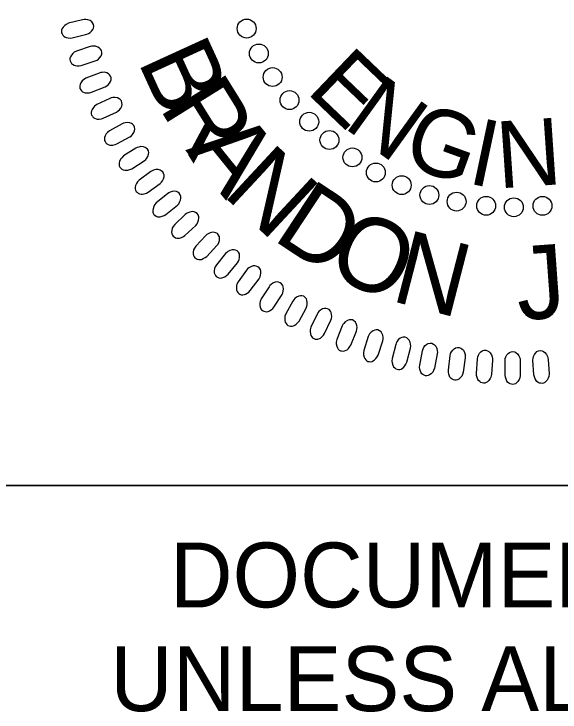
# Model space of a CAD drawing. Extents: x 505602 to 507286, y 483109 to 484209.
# Drawn here: x 507076.9 to 507123.2, y 484026.9 to 484086.2 of the extents above; entities that cross this region are included whole.
import ezdxf

# ---------------------------------------------------------------- set-up
doc = ezdxf.new("R2010")
doc.units = 0
for name, color, linetype in [('Sheet PE Seal Cell', 7, 'Continuous'), ('Sheet Profile CELL', 7, 'Continuous'), ('Sheet Sticker Exception Certification CELL', 7, 'Continuous')]:
    doc.layers.add(name, color=color, linetype=linetype)

msp = doc.modelspace()

# ---------------------------------------------------------------- linework, layer by layer
at = {"layer": 'Sheet PE Seal Cell'}
for points in [[(507082.689, 484085.667), (507081.501, 484085.363), (507081.298, 484085.272), (507081.175, 484085.187), (507081.039, 484085.036), (507080.957, 484084.915), (507080.907, 484084.786), (507080.895, 484084.675), (507080.903, 484084.561), (507080.95, 484084.458), (507081.009, 484084.35), (507081.093, 484084.263), (507081.216, 484084.186), (507081.308, 484084.148), (507081.469, 484084.12), (507081.658, 484084.107), (507081.818, 484084.125), (507083.037, 484084.429), (507083.196, 484084.493), (507083.32, 484084.572), (507083.452, 484084.698), (507083.56, 484084.841), (507083.613, 484084.955), (507083.632, 484085.122), (507083.614, 484085.272), (507083.538, 484085.407), (507083.464, 484085.496), (507083.336, 484085.595), (507083.142, 484085.668), (507082.951, 484085.689), (507082.818, 484085.685)], [(507083.343, 484083.384), (507082.176, 484083.005), (507081.979, 484082.902), (507081.862, 484082.81), (507081.735, 484082.65), (507081.661, 484082.523), (507081.62, 484082.392), (507081.615, 484082.281), (507081.63, 484082.168), (507081.684, 484082.068), (507081.749, 484081.963), (507081.838, 484081.882), (507081.966, 484081.813), (507082.059, 484081.78), (507082.223, 484081.763), (507082.412, 484081.762), (507082.571, 484081.789), (507083.768, 484082.17), (507083.922, 484082.244), (507084.042, 484082.33), (507084.165, 484082.464), (507084.263, 484082.614), (507084.31, 484082.731), (507084.318, 484082.899), (507084.291, 484083.047), (507084.207, 484083.177), (507084.127, 484083.261), (507083.993, 484083.351), (507083.795, 484083.412), (507083.603, 484083.421), (507083.471, 484083.409)], [(507084.102, 484081.146), (507082.961, 484080.696), (507082.77, 484080.58), (507082.659, 484080.48), (507082.543, 484080.313), (507082.477, 484080.182), (507082.444, 484080.049), (507082.446, 484079.937), (507082.468, 484079.825), (507082.528, 484079.729), (507082.6, 484079.628), (507082.693, 484079.553), (507082.825, 484079.493), (507082.921, 484079.466), (507083.086, 484079.459), (507083.274, 484079.469), (507083.431, 484079.507), (507084.602, 484079.962), (507084.752, 484080.045), (507084.865, 484080.138), (507084.98, 484080.28), (507085.069, 484080.436), (507085.108, 484080.556), (507085.105, 484080.724), (507085.069, 484080.87), (507084.977, 484080.994), (507084.892, 484081.073), (507084.753, 484081.155), (507084.551, 484081.203), (507084.359, 484081.2), (507084.228, 484081.18)], [(507085.001, 484078.987), (507083.891, 484078.465), (507083.709, 484078.338), (507083.604, 484078.231), (507083.499, 484078.057), (507083.441, 484077.923), (507083.416, 484077.787), (507083.425, 484077.676), (507083.454, 484077.566), (507083.52, 484077.473), (507083.598, 484077.377), (507083.697, 484077.308), (507083.832, 484077.256), (507083.929, 484077.235), (507084.093, 484077.238), (507084.281, 484077.261), (507084.435, 484077.308), (507085.576, 484077.836), (507085.719, 484077.929), (507085.827, 484078.029), (507085.932, 484078.177), (507086.012, 484078.338), (507086.043, 484078.461), (507086.03, 484078.628), (507085.984, 484078.772), (507085.884, 484078.89), (507085.794, 484078.964), (507085.651, 484079.037), (507085.446, 484079.072), (507085.255, 484079.057), (507085.125, 484079.029)], [(507086.049, 484076.838), (507084.973, 484076.248), (507084.799, 484076.11), (507084.702, 484075.996), (507084.607, 484075.817), (507084.558, 484075.678), (507084.542, 484075.542), (507084.557, 484075.431), (507084.594, 484075.323), (507084.666, 484075.235), (507084.75, 484075.144), (507084.852, 484075.081), (507084.99, 484075.037), (507085.089, 484075.023), (507085.252, 484075.036), (507085.438, 484075.071), (507085.589, 484075.127), (507086.694, 484075.726), (507086.832, 484075.828), (507086.932, 484075.934), (507087.029, 484076.089), (507087.097, 484076.254), (507087.121, 484076.378), (507087.097, 484076.545), (507087.043, 484076.686), (507086.936, 484076.797), (507086.842, 484076.865), (507086.693, 484076.928), (507086.487, 484076.951), (507086.297, 484076.924), (507086.169, 484076.888)], [(507087.205, 484074.764), (507086.169, 484074.106), (507086.003, 484073.958), (507085.914, 484073.839), (507085.83, 484073.653), (507085.79, 484073.513), (507085.783, 484073.375), (507085.805, 484073.265), (507085.848, 484073.16), (507085.926, 484073.076), (507086.015, 484072.991), (507086.121, 484072.935), (507086.261, 484072.9), (507086.36, 484072.892), (507086.523, 484072.915), (507086.707, 484072.961), (507086.853, 484073.027), (507087.919, 484073.694), (507088.05, 484073.803), (507088.144, 484073.917), (507088.23, 484074.077), (507088.288, 484074.247), (507088.304, 484074.372), (507088.27, 484074.537), (507088.207, 484074.673), (507088.093, 484074.778), (507087.995, 484074.84), (507087.842, 484074.894), (507087.635, 484074.904), (507087.447, 484074.865), (507087.322, 484074.82)], [(507088.482, 484072.789), (507087.488, 484072.068), (507087.333, 484071.909), (507087.25, 484071.785), (507087.179, 484071.594), (507087.148, 484071.451), (507087.149, 484071.313), (507087.178, 484071.206), (507087.228, 484071.102), (507087.31, 484071.024), (507087.405, 484070.945), (507087.515, 484070.895), (507087.657, 484070.869), (507087.756, 484070.868), (507087.917, 484070.901), (507088.097, 484070.958), (507088.24, 484071.033), (507089.261, 484071.766), (507089.385, 484071.884), (507089.471, 484072.002), (507089.548, 484072.168), (507089.595, 484072.341), (507089.603, 484072.466), (507089.559, 484072.629), (507089.487, 484072.762), (507089.367, 484072.859), (507089.265, 484072.914), (507089.11, 484072.959), (507088.903, 484072.956), (507088.717, 484072.905), (507088.595, 484072.853)], [(507089.885, 484070.907), (507088.939, 484070.125), (507088.794, 484069.957), (507088.72, 484069.828), (507088.661, 484069.633), (507088.638, 484069.489), (507088.648, 484069.352), (507088.684, 484069.246), (507088.74, 484069.146), (507088.827, 484069.073), (507088.926, 484069), (507089.039, 484068.957), (507089.182, 484068.94), (507089.282, 484068.945), (507089.44, 484068.988), (507089.616, 484069.057), (507089.754, 484069.14), (507090.727, 484069.936), (507090.844, 484070.061), (507090.922, 484070.185), (507090.988, 484070.355), (507091.025, 484070.531), (507091.024, 484070.656), (507090.97, 484070.816), (507090.89, 484070.943), (507090.764, 484071.033), (507090.659, 484071.082), (507090.501, 484071.117), (507090.295, 484071.101), (507090.113, 484071.038), (507089.994, 484070.978)], [(507091.395, 484069.137), (507090.5, 484068.297), (507090.366, 484068.12), (507090.3, 484067.987), (507090.253, 484067.789), (507090.24, 484067.643), (507090.258, 484067.506), (507090.301, 484067.402), (507090.363, 484067.307), (507090.454, 484067.239), (507090.558, 484067.172), (507090.673, 484067.137), (507090.818, 484067.129), (507090.916, 484067.14), (507091.072, 484067.193), (507091.244, 484067.272), (507091.375, 484067.365), (507092.296, 484068.22), (507092.405, 484068.352), (507092.476, 484068.481), (507092.531, 484068.655), (507092.556, 484068.832), (507092.548, 484068.957), (507092.484, 484069.113), (507092.396, 484069.236), (507092.265, 484069.317), (507092.157, 484069.359), (507091.997, 484069.384), (507091.792, 484069.355), (507091.614, 484069.281), (507091.5, 484069.214)], [(507093.131, 484067.359), (507092.29, 484066.464), (507092.167, 484066.279), (507092.11, 484066.142), (507092.075, 484065.941), (507092.071, 484065.794), (507092.098, 484065.66), (507092.147, 484065.559), (507092.215, 484065.468), (507092.31, 484065.406), (507092.419, 484065.346), (507092.535, 484065.317), (507092.68, 484065.319), (507092.778, 484065.335), (507092.93, 484065.398), (507093.096, 484065.488), (507093.222, 484065.589), (507094.088, 484066.5), (507094.187, 484066.639), (507094.25, 484066.772), (507094.294, 484066.949), (507094.308, 484067.127), (507094.292, 484067.252), (507094.219, 484067.403), (507094.123, 484067.521), (507093.987, 484067.593), (507093.876, 484067.628), (507093.716, 484067.644), (507093.513, 484067.601), (507093.34, 484067.517), (507093.23, 484067.443)], [(507094.821, 484065.829), (507094.038, 484064.883), (507093.927, 484064.69), (507093.878, 484064.55), (507093.856, 484064.348), (507093.862, 484064.201), (507093.897, 484064.068), (507093.952, 484063.97), (507094.026, 484063.883), (507094.124, 484063.828), (507094.236, 484063.775), (507094.354, 484063.754), (507094.499, 484063.764), (507094.596, 484063.787), (507094.743, 484063.859), (507094.903, 484063.959), (507095.023, 484064.068), (507095.83, 484065.032), (507095.921, 484065.176), (507095.974, 484065.313), (507096.008, 484065.492), (507096.011, 484065.671), (507095.986, 484065.796), (507095.903, 484065.941), (507095.801, 484066.052), (507095.661, 484066.116), (507095.547, 484066.145), (507095.386, 484066.149), (507095.187, 484066.095), (507095.019, 484065.999), (507094.914, 484065.919)], [(507096.601, 484064.428), (507095.88, 484063.435), (507095.781, 484063.236), (507095.741, 484063.092), (507095.732, 484062.889), (507095.747, 484062.743), (507095.79, 484062.613), (507095.851, 484062.519), (507095.93, 484062.437), (507096.033, 484062.387), (507096.148, 484062.341), (507096.267, 484062.327), (507096.41, 484062.347), (507096.506, 484062.376), (507096.648, 484062.458), (507096.802, 484062.568), (507096.914, 484062.683), (507097.659, 484063.695), (507097.74, 484063.846), (507097.786, 484063.986), (507097.808, 484064.167), (507097.8, 484064.346), (507097.767, 484064.467), (507097.676, 484064.609), (507097.566, 484064.713), (507097.422, 484064.768), (507097.308, 484064.789), (507097.147, 484064.784), (507096.95, 484064.716), (507096.79, 484064.611), (507096.69, 484064.523)], [(507098.503, 484063.015), (507097.846, 484061.979), (507097.759, 484061.774), (507097.728, 484061.628), (507097.732, 484061.424), (507097.756, 484061.28), (507097.808, 484061.153), (507097.874, 484061.062), (507097.959, 484060.986), (507098.063, 484060.942), (507098.181, 484060.903), (507098.301, 484060.898), (507098.443, 484060.926), (507098.536, 484060.962), (507098.673, 484061.051), (507098.82, 484061.171), (507098.924, 484061.294), (507099.604, 484062.35), (507099.676, 484062.506), (507099.713, 484062.648), (507099.723, 484062.83), (507099.703, 484063.008), (507099.663, 484063.128), (507099.564, 484063.263), (507099.448, 484063.359), (507099.3, 484063.406), (507099.185, 484063.42), (507099.025, 484063.404), (507098.833, 484063.325), (507098.679, 484063.209), (507098.585, 484063.116)], [(507100.521, 484061.799), (507099.93, 484060.724), (507099.857, 484060.514), (507099.835, 484060.367), (507099.852, 484060.164), (507099.884, 484060.021), (507099.944, 484059.897), (507100.016, 484059.811), (507100.105, 484059.74), (507100.212, 484059.704), (507100.332, 484059.672), (507100.452, 484059.673), (507100.592, 484059.711), (507100.683, 484059.752), (507100.814, 484059.851), (507100.953, 484059.979), (507101.05, 484060.108), (507101.662, 484061.206), (507101.723, 484061.365), (507101.751, 484061.509), (507101.75, 484061.692), (507101.72, 484061.868), (507101.673, 484061.985), (507101.564, 484062.113), (507101.442, 484062.202), (507101.292, 484062.24), (507101.176, 484062.247), (507101.017, 484062.221), (507100.831, 484062.129), (507100.685, 484062.005), (507100.596, 484061.906)], [(507102.58, 484060.693), (507102.058, 484059.583), (507101.998, 484059.369), (507101.986, 484059.22), (507102.015, 484059.018), (507102.056, 484058.878), (507102.124, 484058.758), (507102.201, 484058.677), (507102.295, 484058.612), (507102.404, 484058.582), (507102.525, 484058.558), (507102.645, 484058.567), (507102.783, 484058.613), (507102.871, 484058.66), (507102.995, 484058.766), (507103.126, 484058.903), (507103.215, 484059.038), (507103.757, 484060.172), (507103.808, 484060.335), (507103.827, 484060.48), (507103.814, 484060.663), (507103.773, 484060.837), (507103.718, 484060.951), (507103.602, 484061.071), (507103.474, 484061.154), (507103.323, 484061.181), (507103.206, 484061.18), (507103.049, 484061.145), (507102.869, 484061.042), (507102.732, 484060.908), (507102.65, 484060.804)], [(507104.708, 484059.685), (507104.256, 484058.544), (507104.21, 484058.326), (507104.207, 484058.177), (507104.249, 484057.978), (507104.298, 484057.84), (507104.374, 484057.725), (507104.456, 484057.649), (507104.553, 484057.589), (507104.664, 484057.567), (507104.787, 484057.55), (507104.906, 484057.567), (507105.04, 484057.622), (507105.125, 484057.674), (507105.243, 484057.788), (507105.364, 484057.933), (507105.444, 484058.073), (507105.914, 484059.238), (507105.956, 484059.404), (507105.965, 484059.55), (507105.941, 484059.732), (507105.888, 484059.903), (507105.827, 484060.013), (507105.703, 484060.127), (507105.571, 484060.2), (507105.418, 484060.218), (507105.302, 484060.21), (507105.147, 484060.164), (507104.974, 484060.051), (507104.845, 484059.908), (507104.77, 484059.799)], [(507106.917, 484058.782), (507106.537, 484057.616), (507106.505, 484057.395), (507106.511, 484057.246), (507106.565, 484057.05), (507106.624, 484056.916), (507106.706, 484056.805), (507106.793, 484056.736), (507106.894, 484056.682), (507107.006, 484056.666), (507107.13, 484056.657), (507107.247, 484056.681), (507107.378, 484056.745), (507107.459, 484056.802), (507107.57, 484056.923), (507107.682, 484057.076), (507107.753, 484057.22), (507108.149, 484058.413), (507108.18, 484058.581), (507108.18, 484058.728), (507108.144, 484058.907), (507108.081, 484059.074), (507108.013, 484059.181), (507107.882, 484059.286), (507107.746, 484059.351), (507107.592, 484059.36), (507107.477, 484059.344), (507107.325, 484059.289), (507107.159, 484059.165), (507107.039, 484059.014), (507106.971, 484058.901)], [(507109.25, 484058.109), (507108.944, 484056.921), (507108.926, 484056.7), (507108.941, 484056.551), (507109.008, 484056.359), (507109.074, 484056.228), (507109.164, 484056.124), (507109.255, 484056.058), (507109.358, 484056.011), (507109.472, 484056.003), (507109.595, 484056.003), (507109.711, 484056.034), (507109.837, 484056.105), (507109.915, 484056.166), (507110.018, 484056.295), (507110.12, 484056.454), (507110.182, 484056.603), (507110.502, 484057.818), (507110.522, 484057.988), (507110.513, 484058.134), (507110.466, 484058.311), (507110.393, 484058.474), (507110.318, 484058.576), (507110.181, 484058.673), (507110.042, 484058.729), (507109.886, 484058.728), (507109.773, 484058.705), (507109.625, 484058.641), (507109.467, 484058.506), (507109.357, 484058.349), (507109.296, 484058.231)], [(507112.772, 484057.322), (507112.541, 484056.116), (507112.463, 484055.908), (507112.386, 484055.781), (507112.244, 484055.635), (507112.128, 484055.546), (507112.003, 484055.489), (507111.892, 484055.469), (507111.778, 484055.471), (507111.673, 484055.511), (507111.56, 484055.563), (507111.469, 484055.641), (507111.385, 484055.759), (507111.341, 484055.848), (507111.303, 484056.008), (507111.278, 484056.196), (507111.286, 484056.357), (507111.514, 484057.592), (507111.568, 484057.755), (507111.639, 484057.883), (507111.757, 484058.023), (507111.893, 484058.139), (507112.003, 484058.2), (507112.168, 484058.229), (507112.32, 484058.22), (507112.458, 484058.153), (507112.552, 484058.084), (507112.658, 484057.963), (507112.743, 484057.774), (507112.776, 484057.584), (507112.781, 484057.452)], [(507115.138, 484056.996), (507114.983, 484055.778), (507114.919, 484055.566), (507114.849, 484055.433), (507114.717, 484055.279), (507114.607, 484055.183), (507114.485, 484055.117), (507114.377, 484055.091), (507114.263, 484055.086), (507114.155, 484055.12), (507114.039, 484055.164), (507113.943, 484055.236), (507113.852, 484055.349), (507113.802, 484055.436), (507113.754, 484055.593), (507113.718, 484055.778), (507113.715, 484055.939), (507113.866, 484057.186), (507113.909, 484057.352), (507113.972, 484057.485), (507114.08, 484057.632), (507114.209, 484057.757), (507114.316, 484057.823), (507114.479, 484057.863), (507114.63, 484057.864), (507114.773, 484057.805), (507114.871, 484057.743), (507114.985, 484057.628), (507115.081, 484057.445), (507115.126, 484057.258), (507115.139, 484057.126)], [(507117.455, 484056.798), (507117.377, 484055.574), (507117.326, 484055.358), (507117.265, 484055.221), (507117.143, 484055.059), (507117.039, 484054.955), (507116.922, 484054.883), (507116.815, 484054.849), (507116.701, 484054.837), (507116.591, 484054.864), (507116.474, 484054.901), (507116.373, 484054.967), (507116.275, 484055.074), (507116.22, 484055.157), (507116.162, 484055.311), (507116.114, 484055.494), (507116.102, 484055.655), (507116.173, 484056.909), (507116.207, 484057.077), (507116.261, 484057.213), (507116.36, 484057.367), (507116.48, 484057.499), (507116.583, 484057.573), (507116.743, 484057.622), (507116.894, 484057.633), (507117.041, 484057.583), (507117.141, 484057.527), (507117.262, 484057.42), (507117.37, 484057.243), (507117.427, 484057.059), (507117.448, 484056.929)], [(507119.808, 484056.726), (507119.808, 484055.499), (507119.77, 484055.281), (507119.718, 484055.14), (507119.606, 484054.971), (507119.508, 484054.861), (507119.396, 484054.781), (507119.292, 484054.742), (507119.18, 484054.722), (507119.068, 484054.742), (507118.948, 484054.772), (507118.843, 484054.831), (507118.738, 484054.932), (507118.679, 484055.011), (507118.611, 484055.161), (507118.552, 484055.34), (507118.529, 484055.5), (507118.522, 484056.756), (507118.545, 484056.926), (507118.59, 484057.065), (507118.679, 484057.225), (507118.791, 484057.365), (507118.889, 484057.445), (507119.046, 484057.504), (507119.196, 484057.524), (507119.345, 484057.484), (507119.45, 484057.434), (507119.577, 484057.335), (507119.696, 484057.165), (507119.764, 484056.985), (507119.793, 484056.856)], [(507122.175, 484056.849), (507122.251, 484055.624), (507122.228, 484055.403), (507122.185, 484055.26), (507122.083, 484055.084), (507121.994, 484054.968), (507121.886, 484054.882), (507121.785, 484054.836), (507121.674, 484054.809), (507121.561, 484054.822), (507121.44, 484054.844), (507121.331, 484054.897), (507121.22, 484054.991), (507121.156, 484055.066), (507121.08, 484055.211), (507121.009, 484055.387), (507120.976, 484055.545), (507120.89, 484056.798), (507120.902, 484056.969), (507120.938, 484057.111), (507121.018, 484057.276), (507121.121, 484057.422), (507121.213, 484057.508), (507121.366, 484057.578), (507121.514, 484057.607), (507121.665, 484057.576), (507121.773, 484057.533), (507121.906, 484057.442), (507122.036, 484057.279), (507122.115, 484057.104), (507122.153, 484056.977)]]:
    msp.add_lwpolyline(points, close=True, dxfattribs=at)
for centre in [(507096.606, 484084.915), (507097.641, 484082.804), (507098.81, 484080.8), (507100.242, 484078.847), (507101.914, 484077.014), (507103.625, 484075.46), (507105.576, 484073.986), (507107.566, 484072.71), (507109.755, 484071.634), (507112.104, 484070.796), (507114.413, 484070.238), (507116.921, 484069.879), (507119.27, 484069.758), (507121.699, 484069.877)]:
    msp.add_circle(centre, 0.801, dxfattribs=at)
at = {"layer": 'Sheet Profile CELL'}
msp.add_lwpolyline([(507069.03, 484158.662), (507169.08, 484158.662), (507169.08, 484046.162), (507069.03, 484046.162)], close=True, dxfattribs=at)
at = {"layer": 'Sheet Sticker Exception Certification CELL'}
msp.add_line((507069.03, 484046.162), (507269.067, 484046.162), dxfattribs=at)
msp.add_line((507069.03, 484046.162), (507269.067, 484046.162), dxfattribs=at)

# ---------------------------------------------------------------- texts
at = {"layer": 'Sheet PE Seal Cell'}
for s, height, rotation, p in [('B', 6.236, 294.5897, (507087.323, 484082.187)), ('E', 5.669, 316.26559, (507101.563, 484079.565)), ('R', 6.236, 301.86473, (507089.134, 484078.23)), ('N', 5.669, 324.20538, (507104.698, 484076.61)), ('G', 5.669, 340.08498, (507109.592, 484073.512)), ('I', 5.669, 348.02477, (507115.221, 484071.822)), ('N', 5.669, 3.90437, (507117.974, 484071.35)), ('A', 6.236, 308.98157, (507091.377, 484074.612)), ('N', 6.236, 317.09274, (507094.456, 484070.864)), ('D', 6.236, 326.58243, (507098.686, 484067.083)), ('O', 6.236, 335.45066, (507103.152, 484064.225)), ('N', 6.236, 345.5505, (507108.704, 484061.853)), ('J', 6.236, 4.1457, (507119.655, 484060.161))]:
    msp.add_text(s, height=height, rotation=rotation, dxfattribs=at).set_placement(p)
at = {"layer": 'Sheet Sticker Exception Certification CELL'}
for s, p in [('DOCUMENT NOT CONSIDERED FINAL', (507090.101, 484035.816)), ('DOCUMENT NOT CONSIDERED FINAL', (507090.101, 484035.816)), ('UNLESS ALL SIGNATURES COMPLETED', (507085.03, 484027.016)), ('UNLESS ALL SIGNATURES COMPLETED', (507085.03, 484027.016))]:
    msp.add_text(s, height=5.5, dxfattribs=at).set_placement(p)

doc.saveas('drawing.dxf')
